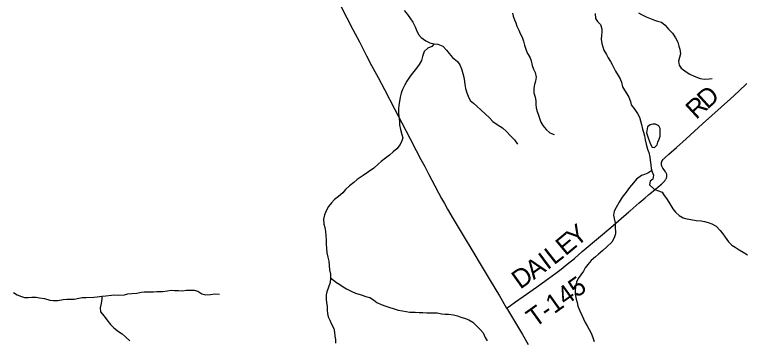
# Model space of a CAD drawing. Extents: x 1442749 to 1756758, y 235267 to 677782.
# Drawn here: x 1612135 to 1623834, y 500562 to 505791 of the extents above; entities that cross this region are included whole.
import ezdxf

# ---------------------------------------------------------------- set-up
doc = ezdxf.new("R2010")
doc.units = 0
for name, color, linetype in [('GM_X_Minor_Lake', 7, 'Continuous'), ('GM_X_Minor_River', 7, 'Continuous'), ('GM_X_State_Route', 7, 'Continuous'), ('GM_X_Township_Road', 7, 'Continuous'), ('GM_X_Township_Road_Text', 7, 'Continuous')]:
    doc.layers.add(name, color=color, linetype=linetype)

msp = doc.modelspace()

# ---------------------------------------------------------------- linework, layer by layer
at = {"layer": 'GM_X_Minor_Lake'}
for points in [[(1622481, 503870), (1622481, 503870), (1622483, 503914), (1622482, 503962), (1622464, 504005), (1622411, 504035), (1622364, 504034), (1622324, 504024), (1622283, 503989), (1622266, 503892), (1622278, 503844), (1622297, 503798)], [(1622297, 503798), (1622311, 503754), (1622328, 503711), (1622354, 503665), (1622394, 503658), (1622433, 503702), (1622445, 503746), (1622468, 503792), (1622481, 503840), (1622481, 503870)]]:
    msp.add_lwpolyline(points, dxfattribs=at)
at = {"layer": 'GM_X_Minor_River'}
for points in [[(1618381, 505858), (1618432, 505791), (1618482, 505724), (1618517, 505668), (1618554, 505595), (1618580, 505541), (1618611, 505474), (1618655, 505421), (1618729, 505369), (1618794, 505340), (1618863, 505321), (1618921, 505316), (1618999, 505285), (1619056, 505222), (1619102, 505166), (1619157, 505105), (1619233, 505038), (1619270, 504987), (1619298, 504923), (1619323, 504848), (1619338, 504788), (1619349, 504720), (1619355, 504667)], [(1620114, 505814), (1620125, 505764), (1620149, 505708), (1620170, 505657), (1620188, 505605), (1620219, 505540), (1620241, 505488), (1620274, 505427), (1620293, 505367), (1620311, 505303), (1620338, 505222), (1620357, 505166), (1620395, 505109), (1620416, 505047), (1620433, 504972), (1620451, 504916), (1620478, 504861), (1620495, 504785), (1620484, 504725), (1620470, 504669), (1620459, 504609), (1620458, 504535), (1620481, 504464), (1620489, 504408), (1620492, 504350), (1620497, 504296), (1620513, 504235), (1620532, 504179), (1620548, 504128), (1620571, 504064), (1620604, 504013), (1620654, 503947), (1620717, 503892), (1620787, 503869)], [(1621444, 505807), (1621447, 505731), (1621480, 505681), (1621526, 505630), (1621549, 505563), (1621551, 505509), (1621544, 505455), (1621537, 505399), (1621550, 505325), (1621564, 505274), (1621583, 505222), (1621621, 505151), (1621652, 505095), (1621690, 505040), (1621715, 504988), (1621743, 504935), (1621768, 504883), (1621813, 504812), (1621843, 504760), (1621864, 504707), (1621881, 504631), (1621911, 504576), (1621950, 504520), (1621980, 504465), (1622007, 504397), (1622021, 504345), (1622078, 504270), (1622121, 504203), (1622151, 504147), (1622170, 504084), (1622183, 504026), (1622203, 503953), (1622214, 503903), (1622232, 503847), (1622245, 503780), (1622258, 503712), (1622279, 503634), (1622303, 503579), (1622318, 503505), (1622325, 503453), (1622336, 503382), (1622342, 503322), (1622357, 503270), (1622375, 503215), (1622366, 503149)], [(1622135, 505820), (1622187, 505791), (1622257, 505756), (1622337, 505721), (1622391, 505704), (1622441, 505688), (1622505, 505669), (1622564, 505624), (1622618, 505557), (1622679, 505493), (1622727, 505420), (1622768, 505351), (1622785, 505285), (1622801, 505234), (1622810, 505164), (1622793, 505104), (1622778, 505042), (1622786, 504982), (1622821, 504931), (1622903, 504870), (1622959, 504837), (1623027, 504805), (1623123, 504767), (1623193, 504755), (1623269, 504760), (1623319, 504767)], [(1618863, 505321), (1618826, 505277), (1618759, 505250), (1618700, 505198), (1618673, 505118), (1618658, 505052), (1618619, 504989), (1618577, 504933), (1618511, 504853), (1618477, 504802), (1618425, 504724), (1618389, 504662), (1618353, 504590), (1618331, 504531), (1618316, 504467), (1618305, 504396), (1618296, 504340), (1618291, 504272), (1618289, 504212), (1618296, 504154), (1618303, 504072), (1618306, 504021), (1618322, 503947), (1618345, 503866), (1618358, 503814), (1618345, 503764), (1618315, 503704), (1618260, 503637), (1618205, 503587), (1618144, 503536), (1618079, 503488), (1618012, 503435), (1617961, 503393), (1617892, 503328), (1617725, 503210)], [(1619355, 504667), (1619364, 504607), (1619385, 504535), (1619405, 504480), (1619438, 504412), (1619490, 504369), (1619543, 504322), (1619613, 504255), (1619679, 504200), (1619746, 504133), (1619802, 504077), (1619871, 504026), (1619955, 503973), (1620021, 503914), (1620082, 503847), (1620150, 503780), (1620195, 503711)], [(1622352, 503287), (1622285, 503246), (1622234, 503227), (1622182, 503209), (1622104, 503152)], [(1617725, 503210), (1617624, 503142), (1617571, 503098), (1617505, 503041), (1617442, 502985), (1617395, 502928), (1617325, 502874), (1617262, 502821), (1617214, 502769), (1617169, 502711), (1617133, 502654), (1617102, 502576), (1617087, 502508), (1617094, 502427), (1617108, 502373), (1617117, 502309), (1617125, 502245), (1617128, 502173), (1617132, 502110), (1617133, 502038), (1617140, 501968), (1617158, 501900), (1617171, 501834), (1617177, 501765), (1617182, 501695), (1617197, 501627), (1617197, 501563), (1617192, 501493), (1617161, 501401), (1617141, 501343), (1617130, 501291), (1617130, 501223), (1617135, 501167), (1617147, 501114), (1617148, 501048), (1617149, 500996), (1617163, 500942), (1617187, 500886), (1617216, 500821), (1617251, 500755), (1617265, 500692), (1617270, 500628), (1617278, 500576), (1617277, 500520)], [(1622104, 503152), (1622055, 503090), (1621994, 503014), (1621937, 502941), (1621876, 502859), (1621824, 502781), (1621777, 502694), (1621744, 502638), (1621738, 502572), (1621745, 502516), (1621761, 502451), (1621762, 502399), (1621765, 502271), (1621748, 502209), (1621708, 502137), (1621631, 502064), (1621566, 502006), (1621496, 501945), (1621445, 501905), (1621378, 501844), (1621326, 501780), (1621283, 501726), (1621255, 501672), (1621210, 501617), (1621171, 501555), (1621143, 501495), (1621124, 501427), (1621122, 501357), (1621123, 501303), (1621138, 501224), (1621154, 501168), (1621165, 501110), (1621195, 501036), (1621228, 500967), (1621256, 500907), (1621281, 500848), (1621313, 500794), (1621344, 500738), (1621376, 500677), (1621405, 500609), (1621427, 500545)], [(1622366, 503149), (1622326, 503116), (1622311, 503058), (1622387, 502991), (1622442, 502966), (1622514, 502939), (1622550, 502889), (1622585, 502837), (1622621, 502780), (1622657, 502728), (1622688, 502673), (1622732, 502619), (1622789, 502568), (1622853, 502528), (1622911, 502511), (1622977, 502500), (1623063, 502486), (1623139, 502483), (1623195, 502468), (1623253, 502456), (1623313, 502431), (1623379, 502393), (1623448, 502326), (1623488, 502275), (1623523, 502219), (1623577, 502146), (1623630, 502092), (1623686, 502059), (1623750, 502014), (1623812, 501980), (1623886, 501937)], [(1617197, 501567), (1617296, 501494), (1617350, 501457), (1617402, 501421), (1617458, 501392), (1617539, 501349), (1617599, 501321), (1617689, 501294), (1617763, 501267), (1617831, 501250), (1617891, 501212), (1617944, 501171), (1618014, 501137), (1618084, 501112), (1618148, 501091), (1618202, 501075), (1618282, 501050), (1618352, 501035), (1618470, 501016), (1618558, 501013), (1618622, 501009), (1618680, 501008), (1618742, 501006), (1618796, 501003), (1618911, 501002), (1618985, 500990), (1619039, 500983), (1619093, 500981), (1619169, 500972), (1619237, 500955), (1619291, 500937), (1619347, 500920), (1619418, 500891), (1619480, 500857), (1619548, 500786), (1619605, 500731), (1619649, 500681), (1619680, 500608), (1619710, 500556)], [(1612119, 501331), (1612177, 501292), (1612244, 501265), (1612296, 501252), (1612355, 501253), (1612411, 501257), (1612479, 501258), (1612537, 501245), (1612615, 501232), (1612699, 501207), (1612751, 501200), (1612829, 501205), (1612912, 501218), (1612974, 501225), (1613092, 501224), (1613167, 501239), (1613219, 501248), (1613283, 501251), (1613403, 501254), (1613458, 501261), (1613536, 501270), (1613598, 501277), (1613689, 501290), (1613741, 501296), (1613805, 501289), (1613895, 501294), (1613950, 501307), (1614016, 501314), (1614094, 501321), (1614165, 501338), (1614215, 501342), (1614295, 501341), (1614363, 501344), (1614418, 501349), (1614506, 501348), (1614586, 501355), (1614646, 501368), (1614698, 501365), (1614765, 501361), (1614819, 501360), (1614893, 501371), (1614965, 501370), (1615015, 501367), (1615073, 501350), (1615137, 501308)], [(1615137, 501308), (1615203, 501292), (1615277, 501300), (1615347, 501311), (1615421, 501304)], [(1613532, 501270), (1613533, 501222), (1613524, 501154), (1613507, 501084), (1613513, 501018), (1613570, 500953), (1613613, 500894), (1613672, 500817), (1613726, 500765), (1613801, 500706), (1613859, 500669), (1613916, 500616), (1613980, 500555)]]:
    msp.add_lwpolyline(points, dxfattribs=at)
at = {"layer": 'GM_X_State_Route'}
msp.add_lwpolyline([(1617364, 505927), (1617462, 505737), (1617559, 505551), (1617662, 505353), (1617778, 505129), (1617859, 504975), (1617961, 504780), (1618063, 504589), (1618230, 504266), (1618342, 504054), (1618476, 503795), (1618573, 503612), (1618649, 503467), (1618710, 503351), (1618774, 503225), (1618871, 503042), (1618929, 502932), (1618980, 502840), (1619025, 502760), (1619076, 502669), (1619168, 502513), (1619263, 502353), (1619344, 502217), (1619467, 502015), (1619631, 501739), (1619758, 501525), (1619906, 501277), (1620023, 501081), (1620037, 501057), (1620146, 500873), (1620276, 500657), (1620370, 500495)], dxfattribs=at)
at = {"layer": 'GM_X_Township_Road'}
msp.add_lwpolyline([(1620023, 501081), (1620062, 501108), (1620165, 501179), (1620290, 501269), (1620502, 501418), (1620692, 501553), (1620812, 501640), (1620898, 501705), (1620995, 501784), (1621108, 501879), (1621235, 501987), (1621496, 502207), (1621693, 502376), (1621980, 502625), (1621990, 502634), (1622002, 502644), (1622148, 502768), (1622242, 502849), (1622290, 502891), (1622304, 502903), (1622317, 502914), (1622407, 502989), (1622482, 503053), (1622505, 503072), (1622534, 503098), (1622543, 503108), (1622552, 503118), (1622558, 503125), (1622565, 503134), (1622570, 503142), (1622575, 503151), (1622579, 503158), (1622583, 503167), (1622586, 503177), (1622588, 503186), (1622590, 503196), (1622590, 503208), (1622590, 503217), (1622588, 503227), (1622586, 503236), (1622584, 503243), (1622580, 503252), (1622576, 503259), (1622570, 503270), (1622546, 503302), (1622529, 503326), (1622517, 503346), (1622512, 503357), (1622509, 503366), (1622507, 503375), (1622505, 503385), (1622504, 503394), (1622505, 503403), (1622506, 503413), (1622507, 503421), (1622510, 503428), (1622513, 503436), (1622518, 503447), (1622524, 503456), (1622529, 503463), (1622534, 503470), (1622541, 503478), (1622551, 503488), (1622562, 503498), (1622624, 503552), (1622743, 503656), (1622900, 503799), (1623163, 504037), (1623609, 504439), (1623744, 504564), (1623874, 504684)], dxfattribs=at)

# ---------------------------------------------------------------- texts
at = {"layer": 'GM_X_Township_Road_Text'}
for s, rotation, p in [('D', 42.1088, (1623242, 504263)), ('R', 42.4436, (1623061, 504097)), ('Y', 39.902, (1621139, 502053)), ('E', 39.7726, (1620966, 501909)), ('L', 38.1877, (1620782, 501764)), ('I', 36.4798, (1620676, 501685)), ('A', 35.4864, (1620456, 501528)), ('D', 35.4017, (1620240, 501375)), ('T-145', 35.5785, (1620476, 500760))]:
    msp.add_text(s, height=300, rotation=rotation, dxfattribs=at).set_placement(p)

doc.saveas('drawing.dxf')
